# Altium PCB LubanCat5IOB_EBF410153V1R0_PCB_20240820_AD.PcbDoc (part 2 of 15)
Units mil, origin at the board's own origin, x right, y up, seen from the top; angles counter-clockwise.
Board outline 6811.02 x 4055.12 mil, 6 copper layers (TOP, GND02, ART03, ART04, PWR05, BOTTOM), stack 59.279 mil thick; 981 components, 783 nets, 3627 pads, 2669 vias.
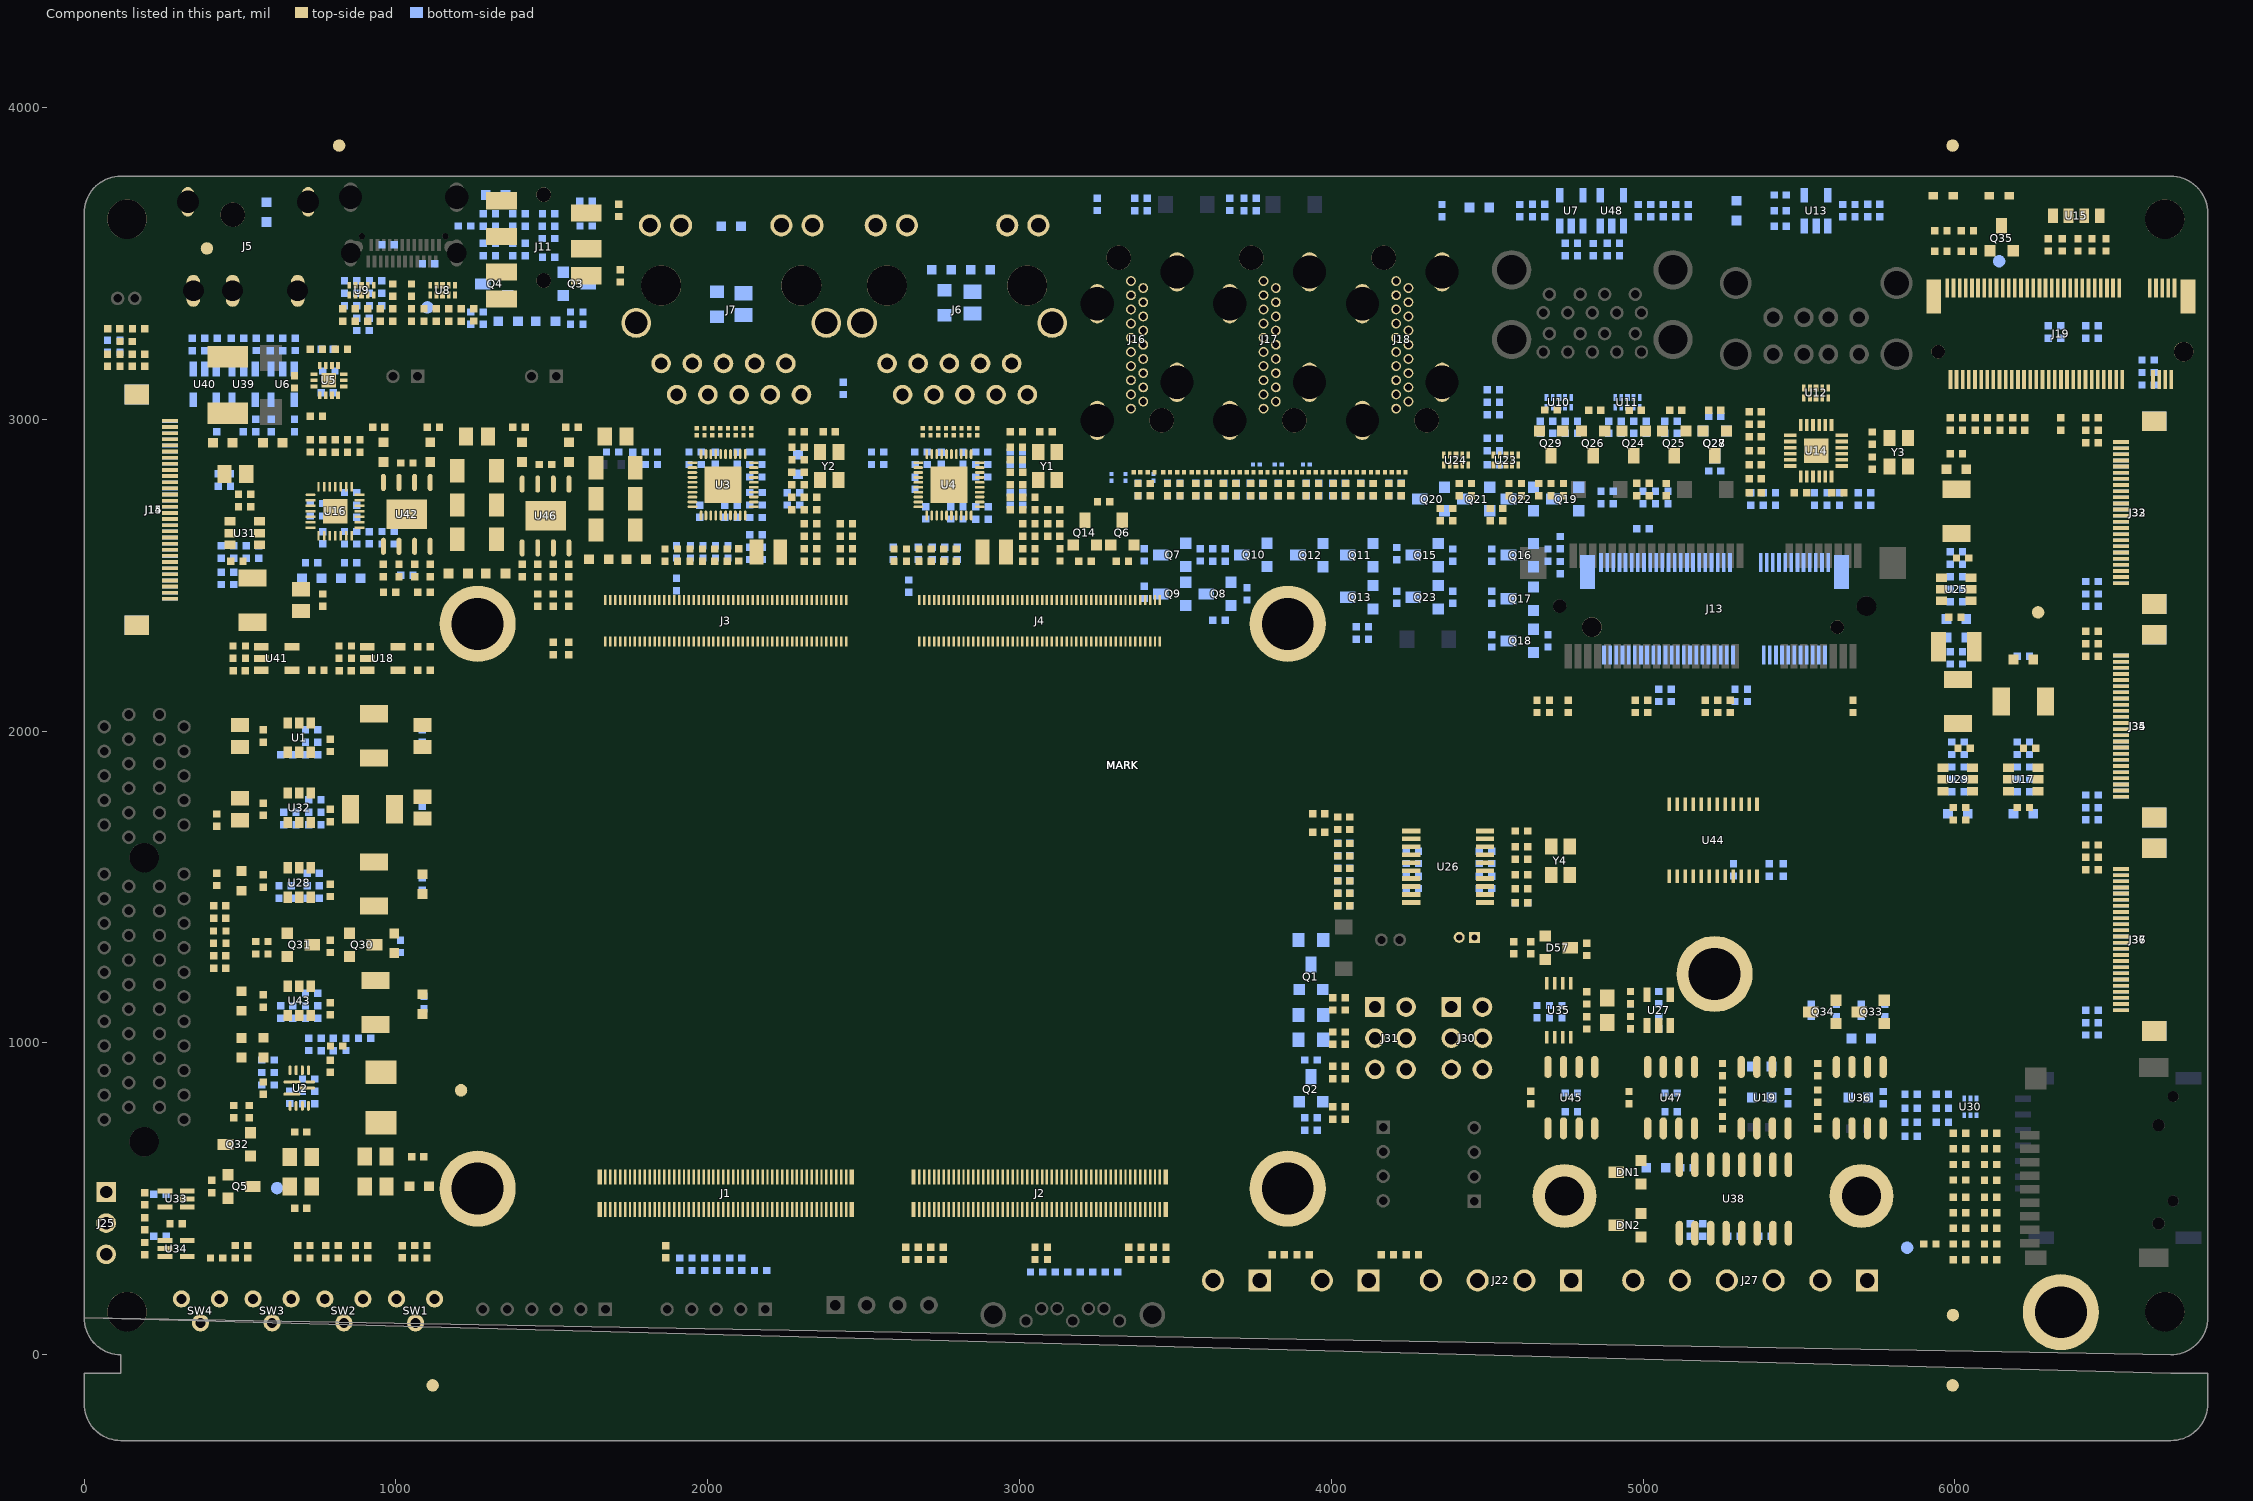
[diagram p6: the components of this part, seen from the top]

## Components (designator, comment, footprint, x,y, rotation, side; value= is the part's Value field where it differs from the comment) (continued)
Q9 "2SK3018_SOT23_IC_2SK3018" SOT23#1 3490,2440 r270 bottom
Q10 "2SK3018_SOT23_IC_2SK3018" SOT23#1 3750,2565 r270 bottom
Q11 "2SK3018_SOT23_IC_2SK3018" SOT23#1 4090,2564.37 r270 bottom
Q12 "2SK3018_SOT23_IC_2SK3018" SOT23#1 3930,2564.37 r270 bottom
Q13 "2SK3018_SOT23_IC_2SK3018" SOT23#1 4090,2429.37 r270 bottom
Q14 "2SK3018_SOT23_IC_2SK3018" SOT23#1 3210,2640 r0 top
Q15 "2SK3018_SOT23_IC_2SK3018" SOT23#1 4300,2564.37 r270 bottom
Q16 "2SK3018_SOT23_IC_2SK3018" SOT23#1 4605,2564.37 r270 bottom
Q17 "2SK3018_SOT23_IC_2SK3018" SOT23#1 4605,2424.37 r270 bottom
Q18 "2SK3018_SOT23_IC_2SK3018" SOT23#1 4605,2289.37 r270 bottom
Q19 "2SK3018_SOT23_IC_2SK3018" SOT23#1 4750,2744.37 r270 bottom
Q20 "2SK3018_SOT23_IC_2SK3018" SOT23#1 4320,2744.37 r270 bottom
Q21 "2SK3018_SOT23_IC_2SK3018" SOT23#1 4465,2744.37 r270 bottom
Q22 "2SK3018_SOT23_IC_2SK3018" SOT23#1 4605,2744.37 r270 bottom
Q23 "2SK3018_SOT23_IC_2SK3018" SOT23#1 4300,2429.37 r270 bottom
Q24 "2SK3018_SOT23_IC_2SK3018" SOT23#1 4970,2919.37 r180 top
Q25 "2SK3018_SOT23_IC_2SK3018" SOT23#1 5100,2919.37 r180 top
Q26 "2SK3018_SOT23_IC_2SK3018" SOT23#1 4840,2919.37 r180 top
Q27 "MOSFET_P_SOT23_IC_SSM3J328R-LF" SOT23#1 5230,2919.37 r180 top
Q28 "NPN_SOT23_IC_SS8050" SOT23#1 5230,2919.37 r0 bottom
Q29 "NPN_SOT23_IC_SS8050" SOT23#1 4705,2919.37 r180 top
Q30 "MOSFET_P_SOT23_IC_SSM3J328R-LF" SOT23#1 895,1314.37 r270 top
Q31 "NPN_SOT23_IC_SS8050" SOT23#1 695,1314.37 r270 top
Q32 "NPN_SOT23_IC_SS8050" SOT23#1 490,674.37 r90 top
Q33 "2SK3018_SOT23_IC_2SK3018" SOT23#1 5730,1099.37 r90 top
Q34 "2SK3018_SOT23_IC_2SK3018" SOT23#1 5575,1099.37 r90 top
Q35 "NPN_SOT23_IC_SS8050" SOT23#1 6150,3584.37 r0 top
R1 "RES_R0402_DISCRETE_100R" R0402#1 1020,330 r90 top
R2 "RES_R0402_DISCRETE_100R" R0402#1 890,350 r0 top
R3 "RES_R0402_DISCRETE_10K" R0402#1 4740,1100 r270 bottom
R4 "RES_R0402_DISCRETE_115K" R0402#1 730,1924.37 r0 bottom
R5 "RES_R0402_DISCRETE_100R" R0402#1 795,350 r0 top
R6 "RES_R0402_DISCRETE_1K" R0402#2 650,1924.37 r0 bottom
R7 "RES_R0402_DISCRETE_20K" R0402#1 730,2004.37 r0 bottom
R8 "RES_R0402_DISCRETE_3.3R" R0402#1 790,925.04 r90 top
R9 "RES_R0402_DISCRETE_510K" R0402#1 590,945.04 r0 bottom
R10 "RES_R0402_DISCRETE_NC" R0402#2 900,1015 r0 bottom
R11 "RES_R0402_DISCRETE_4.7K" R0402#1 5955,3604.37 r0 top
R12 "RES_R0402_DISCRETE_43K" R0402#2 780,975.04 r0 bottom
R13 "RES_R0402_DISCRETE_NC" R0402#1 780,1015.04 r0 bottom
R14 "RES_R0402_DISCRETE_100K" R0402#1 720,845.04 r0 bottom
R15 "RES_R0402_DISCRETE_100K" R0402#1 660,825.04 r270 bottom
R16 "RES_R0402_DISCRETE_100K" R0402#2 590,905.04 r0 bottom
R17 "RES_R0402_DISCRETE_7.5K" R0402#1 720,995.04 r90 bottom
R18 "RES_R0402_DISCRETE_NC" R0402#2 720,805.04 r0 bottom
R19 "RES_R0402_DISCRETE_100R" R0402#1 505,350 r0 top
R20 "RES_R0402_DISCRETE_4.7K" R0402#1 2720,2570 r270 bottom
R21 "RES_R0402_DISCRETE_4.7K" R0402#1 2675,2570 r270 bottom
R22 "RES_R0402_DISCRETE_4.7K" R0402#1 2595,2570 r270 bottom
R23 "RES_R0402_DISCRETE_22R" R0402#1 2717.62,2564.37 r90 top
R24 "RES_R0402_DISCRETE_22R" R0402#1 2677.62,2564.37 r90 top
R25 "RES_R0402_DISCRETE_2.49K" R0402#2 2879,2855 r0 bottom
R26 "RES_R0402_DISCRETE_22R" R0402#1 2637.62,2564.37 r90 top
R27 "RES_R0402_DISCRETE_22R" R0402#1 2597.62,2564.37 r90 top
R28 "RES_R0402_DISCRETE_22R" R0402#1 2797.62,2564.37 r90 top
R29 "RES_R0402_DISCRETE_22R" R0402#1 2757.62,2564.37 r90 top
R30 "RES_R0402_DISCRETE_4.7K" R0402#1 2645,2465 r270 bottom
R31 "RES_R0402_DISCRETE_4.7K" R0402#1 2800,2570 r90 bottom
R32 "RES_R0402_DISCRETE_4.7K" R0402#1 2760,2570 r90 bottom
R33 "RES_R0402_DISCRETE_4.7K" R0402#1 2545,2895 r0 bottom
R34 "RES_R0402_DISCRETE_4.7K" R0402#1 2545,2855 r0 bottom
R35 "RES_R0402_DISCRETE_4.7K" R0402#1 2880,2680 r0 bottom
R36 "RES_R0402_DISCRETE_115K" R0402#1 520,2574.37 r270 bottom
R37 "RES_R0402_DISCRETE_22R" R0402#1 2970,2745 r90 bottom
R38 "RES_R0402_DISCRETE_NC" R0402#1 3010,2745 r90 bottom
R39 "RES_R0603_DISCRETE_510R" R0603#1 2750,3479.37 r0 bottom
R40 "RES_R0603_DISCRETE_510R" R0603#2 2875,3479.37 r0 bottom
R41 "RES_R0402_DISCRETE_10K" R0402#1 2665,2795 r90 bottom
R42 "RES_R0805_DISCRETE_1M" R0805#1 2760,3374.37 r90 bottom
R43 "RES_R0402_DISCRETE_4.7K" R0402#1 2990,2855 r0 bottom
R44 "RES_R0402_DISCRETE_4.7K" R0402#1 2970,2730 r90 top
R45 "RES_R0402_DISCRETE_4.7K" R0402#2 2880,2720 r0 bottom
R46 "RES_R0402_DISCRETE_0R" R0402#1 3010,2645 r270 top
R47 "RES_R0402_DISCRETE_0R" R0402#1 3050,2645 r90 top
R48 "RES_R0402_DISCRETE_4.7K" R0402#1 1985,2575 r270 bottom
R49 "RES_R0402_DISCRETE_4.7K" R0402#1 1945,2575 r270 bottom
R50 "RES_R0402_DISCRETE_4.7K" R0402#1 1900,2575 r270 bottom
R51 "RES_R0402_DISCRETE_22R" R0402#1 1983.21,2564.37 r90 top
R52 "RES_R0402_DISCRETE_22R" R0402#1 1943.21,2564.37 r90 top
R53 "RES_R0402_DISCRETE_2.49K" R0402#2 2154.59,2855 r0 bottom
R54 "RES_R0402_DISCRETE_22R" R0402#1 1903.21,2564.37 r90 top
R55 "RES_R0402_DISCRETE_22R" R0402#1 1863.21,2564.37 r90 top
R56 "RES_R0402_DISCRETE_22R" R0402#1 2063.21,2564.37 r90 top
R57 "RES_R0402_DISCRETE_22R" R0402#1 2023.21,2564.37 r90 top
R58 "RES_R0402_DISCRETE_4.7K" R0402#1 1900,2470 r270 bottom
R59 "RES_R0402_DISCRETE_4.7K" R0402#1 2065,2575 r90 bottom
R60 "RES_R0402_DISCRETE_4.7K" R0402#1 2025,2575 r90 bottom
R61 "RES_R0402_DISCRETE_4.7K" R0402#1 1819.59,2895 r0 bottom
R62 "RES_R0402_DISCRETE_4.7K" R0402#1 1819.59,2855 r0 bottom
R63 "RES_R0402_DISCRETE_4.7K" R0402#1 2155,2685 r0 bottom
R64 "RES_R0603_DISCRETE_510R" R0603#1 2290,2855 r270 bottom
R65 "RES_R0402_DISCRETE_1K" R0402#1 440,2574.37 r270 bottom
R66 "RES_R0603_DISCRETE_510R" R0603#1 2075,3619.37 r0 bottom
R67 "RES_R0402_DISCRETE_100R" R0402#1 2255,2745 r90 bottom
R68 "RES_R0402_DISCRETE_120R" R0402#1 2295,2745 r90 bottom
R69 "RES_R0402_DISCRETE_10K" R0402#1 1695,2895 r0 bottom
R70 "RES_R0402_DISCRETE_NC" R0402#1 1760,2875 r90 bottom
R71 "RES_R0805_DISCRETE_1M" R0805#1 2030,3369.37 r90 bottom
R72 "RES_R0402_DISCRETE_4.7K" R0402#1 2270,2730 r90 top
R73 "RES_R0402_DISCRETE_4.7K" R0402#2 2155,2765 r0 bottom
R74 "RES_R0402_DISCRETE_4.7K" R0402#2 2155,2725 r0 bottom
R75 "RES_R0402_DISCRETE_0R" R0402#1 2350,2645 r270 top
R76 "RES_R0402_DISCRETE_0R" R0402#1 2310,2645 r90 top
R77 "RES_R0402_DISCRETE_4.7K" R0402#1 2445,2545 r180 top
R78 "RES_R0402_DISCRETE_NC" R0402#1 2445,2585 r180 top
R79 "RES_R0402_DISCRETE_2.2R" R0402#1 4790,2974.37 r270 bottom
R80 "RES_R0402_DISCRETE_2.2R" R0402#1 4750,2974.37 r270 bottom
R81 "RES_R0402_DISCRETE_2.2R" R0402#1 1050,3334.37 r270 top
R82 "RES_R0402_DISCRETE_2.2R" R0402#1 990,3334.37 r270 top
R83 "RES_R0402_DISCRETE_0R" R0402#1 4710,2974.37 r270 bottom
R84 "RES_R0402_DISCRETE_0R" R0402#1 4670,2974.37 r270 bottom
R85 "RES_R0402_DISCRETE_0R" R0402#1 1170,3334.37 r270 top
R86 "RES_R0402_DISCRETE_0R" R0402#1 1210,3334.37 r270 top
R87 "RES_R0402_DISCRETE_10K" R0402#1 745,3010 r0 top
R88 "RES_R0402_DISCRETE_2.2R" R0402#1 4930,2974.37 r270 bottom
R89 "RES_R0402_DISCRETE_0R" R0402#1 910,3334.37 r270 top
R90 "RES_R0402_DISCRETE_2.2R" R0402#1 4890,2974.37 r270 bottom
R91 "RES_R0402_DISCRETE_0R" R0402#1 950,3334.37 r270 top
R92 "RES_R0402_DISCRETE_100K" R0402#1 935,3364.37 r0 bottom
R93 "RES_R0402_DISCRETE_1K" R0402#1 600,2980 r90 bottom
R94 "RES_R0402_DISCRETE_100K" R0402#2 855,3364.37 r0 bottom
R95 "RES_R0402_DISCRETE_3.4K" R0402#1 677,3240.37 r90 bottom
R96 "RES_R0402_DISCRETE_1K" R0402#1 4605,3669.37 r90 bottom
R97 "RES_R0402_DISCRETE_NC" R0402#1 935,3404.37 r0 bottom
R98 "RES_R0402_DISCRETE_NC" R0402#2 855,3404.37 r0 bottom
R99 "RES_R0402_DISCRETE_3.4K" R0402#2 4665,3649.37 r0 bottom
R100 "RES_R0402_DISCRETE_0R" R0402#1 5385,2744.37 r90 bottom
R101 "RES_R0402_DISCRETE_10K" R0402#1 5360,2854.37 r180 top
R102 "RES_R0402_DISCRETE_1K" R0402#1 5440,3719.37 r0 bottom
R103 "RES_R0402_DISCRETE_3.4K" R0402#2 5440,3619.37 r0 bottom
R104 "RES_R0402_DISCRETE_100K" R0402#1 5360,2764.37 r180 top
R105 "RES_R0402_DISCRETE_100K" R0402#1 5360,2899.37 r180 top
R106 "RES_R0402_DISCRETE_2.2R" R0402#1 5360,2944.37 r180 top
R107 "RES_R0402_DISCRETE_2.2R" R0402#1 5360,2984.37 r180 top
R108 "RES_R0402_DISCRETE_2.7K" R0402#1 5360,3024.37 r180 top
R109 "RES_R0402_DISCRETE_10K" R0402#1 6345,3559.37 r90 top
R110 "RES_R0402_DISCRETE_22R" R0402#1 6300,3559.37 r90 top
R111 "RES_R0402_DISCRETE_22R" R0402#1 6485,3559.37 r270 top
R112 "RES_R0402_DISCRETE_4.7R" R0402#1 915,2620 r90 bottom
R113 "RES_R0402_DISCRETE_100R" R0402#1 1490,3519.37 r0 bottom
R114 "RES_R0402_DISCRETE_0R" R0402#1 1470,3599.37 r270 bottom
R115 "RES_R0402_DISCRETE_2.2K" R0402#2 1300,3619.37 r0 bottom
R116 "RES_R0402_DISCRETE_100K" R0402#1 1300,3659.37 r0 bottom
R117 "RES_R0402_DISCRETE_0R" R0402#1 1510,3599.37 r270 bottom
R118 "RES_R0402_DISCRETE_100K" R0402#1 1395,3659.37 r0 bottom
R119 "RES_R0402_DISCRETE_100K" R0402#1 1630,3679.37 r270 bottom
R120 "RES_R0402_DISCRETE_0R" R0402#1 1590,3679.37 r90 bottom
R121 "RES_R0402_DISCRETE_10K" R0402#1 725,2915 r270 top
R122 "RES_R0402_DISCRETE_0R" R0402#1 1560,3324.37 r270 bottom
R123 "RES_R0402_DISCRETE_470R" R0402#1 1600,3324.37 r270 bottom
R124 "RES_R0402_DISCRETE_0R" R0402#1 1280,3324.37 r270 bottom
R125 "RES_R0402_DISCRETE_100R" R0402#1 115,3234.37 r270 bottom
R126 "RES_R0402_DISCRETE_1.1K" R0402#1 75,3189.37 r90 top
R127 "RES_R0805_DISCRETE_0R" R0805#2 3935,1090 r0 bottom
R128 "RES_R0402_DISCRETE_4.7K" R0402#1 6040,3604.37 r0 top
R129 "RES_R0805_DISCRETE_0R" R0805#1 3935,1330 r0 bottom
R130 "RES_R0402_DISCRETE_0R" R0402#1 115,3189.37 r270 top
R131 "RES_R0805_DISCRETE_NC" R0805#2 3935,1010 r0 bottom
R132 "RES_R0402_DISCRETE_10K" R0402#1 3935,945 r0 bottom
R133 "RES_R0402_DISCRETE_1K" R0402#1 3935,720 r0 bottom
R134 "RES_R0402_DISCRETE_0R" R0402#1 155,3189.37 r270 top
R135 "RES_R0402_DISCRETE_10K" R0402#2 3935,760 r0 bottom
R136 "RES_R0402_DISCRETE_1.1K" R0402#1 195,3189.37 r270 top
R137 "RES_R0402_DISCRETE_0R" R0402#1 455,1339.37 r90 top
R138 "RES_R0402_DISCRETE_100K" R0402#2 6220,1925 r0 bottom
R139 "RES_R0402_DISCRETE_10K" R0402#2 6220,1805 r0 bottom
R140 "RES_R0402_DISCRETE_1K" R0402#2 6220,1845 r0 bottom
R141 "RES_R0402_DISCRETE_30K" R0402#2 6220,1885 r0 bottom
R142 "RES_R0402_DISCRETE_2.2R" R0402#1 5590,2744.37 r270 bottom
R143 "RES_R0402_DISCRETE_2.2R" R0402#1 5550,2744.37 r270 bottom
R144 "RES_R0402_DISCRETE_1K" R0402#1 5090,2114.37 r270 bottom
R145 "RES_R0402_DISCRETE_22R" R0402#1 5080,2749.37 r270 bottom
R146 "RES_R0402_DISCRETE_1K" R0402#1 5050,2114.37 r270 bottom
R147 "RES_R0402_DISCRETE_4.7K" R0402#1 5040,2749.37 r270 bottom
R148 "RES_R0402_DISCRETE_22R" R0402#1 5000,2749.37 r270 bottom
R149 "RES_R0402_DISCRETE_20K" R0402#1 5105,3669.37 r270 bottom
R150 "RES_R0402_DISCRETE_10K" R0402#1 5065,3669.37 r90 bottom
R151 "RES_R0402_DISCRETE_4.7K" R0402#1 3330,2545 r0 top
R152 "RES_R0402_DISCRETE_4.7K" R0402#1 3270,2735 r0 top
R153 "RES_R0402_DISCRETE_1K" R0402#2 3640,2585 r0 bottom
R154 "RES_R0402_DISCRETE_4.7K" R0402#2 3640,2545 r0 bottom
R155 "RES_R0402_DISCRETE_4.7K" R0402#1 3400,2565 r90 bottom
R156 "RES_R0402_DISCRETE_0R" R0402#1 3250,3689.37 r90 bottom
R157 "RES_R0402_DISCRETE_47K" R0402#2 3640,2355 r0 bottom
R158 "RES_R0402_DISCRETE_47K" R0402#1 3730,2440 r90 bottom
R159 "RES_R0402_DISCRETE_1.2K" R0402#1 3380,2775 r90 bottom
R160 "RES_R0402_DISCRETE_47K" R0402#1 3400,2445 r270 bottom
R161 "RES_R0402_DISCRETE_499R" R0402#1 3475,2775 r270 bottom
R162 "RES_R0402_DISCRETE_499R" R0402#1 3515,2775 r270 bottom
R163 "RES_R0402_DISCRETE_499R" R0402#1 3740,2775 r270 bottom
R164 "RES_R0402_DISCRETE_499R" R0402#1 3780,2775 r270 bottom
R165 "RES_R0402_DISCRETE_499R" R0402#1 3655,2775 r270 bottom
R166 "RES_R0402_DISCRETE_499R" R0402#1 3695,2775 r270 bottom
R167 "RES_R0402_DISCRETE_499R" R0402#1 3565,2775 r270 bottom
R168 "RES_R0402_DISCRETE_499R" R0402#1 3605,2775 r270 bottom
R169 "RES_R0402_DISCRETE_1K" R0402#1 4100,2294.37 r0 bottom
R170 "RES_R0402_DISCRETE_27K" R0402#1 3210,2545 r0 top
R171 "RES_R0402_DISCRETE_10K" R0402#2 4100,2334.37 r0 bottom
R172 "RES_R0402_DISCRETE_4.7K" R0402#1 4390,2564.37 r270 bottom
R173 "RES_R0402_DISCRETE_10K" R0402#1 4210,2569.37 r90 bottom
R174 "RES_R0402_DISCRETE_1K" R0402#1 4735,2604.37 r270 bottom
R175 "RES_R0402_DISCRETE_4.7K" R0402#1 4735,2524.37 r90 bottom
R176 "RES_R0402_DISCRETE_10K" R0402#1 4515,2564.37 r90 bottom
R177 "RES_R0402_DISCRETE_0R" R0402#1 3675,3689.37 r90 bottom
R178 "RES_R0402_DISCRETE_47K" R0402#1 4515,2429.37 r270 bottom
R179 "RES_R0402_DISCRETE_47K" R0402#1 4515,2289.37 r90 bottom
R180 "RES_R0402_DISCRETE_1.2K" R0402#1 3830,2775 r90 bottom
R181 "RES_R0402_DISCRETE_47K" R0402#1 4695,2289.37 r270 bottom
R182 "RES_R0402_DISCRETE_499R" R0402#1 3920,2775 r270 bottom
R183 "RES_R0402_DISCRETE_499R" R0402#1 3960,2775 r270 bottom
R184 "RES_R0402_DISCRETE_499R" R0402#1 4185,2775 r270 bottom
R185 "RES_R0402_DISCRETE_499R" R0402#1 4225,2775 r270 bottom
R186 "RES_R0402_DISCRETE_499R" R0402#1 4095,2775 r270 bottom
R187 "RES_R0402_DISCRETE_499R" R0402#1 4135,2774.37 r270 bottom
R188 "RES_R0402_DISCRETE_499R" R0402#1 4005,2775 r270 bottom
R189 "RES_R0402_DISCRETE_499R" R0402#1 4045,2775 r270 bottom
R190 "RES_R0402_DISCRETE_1K" R0402#1 4905,2749.37 r90 bottom
R191 "RES_R0402_DISCRETE_27K" R0402#1 4390,2429.37 r270 bottom
R192 "RES_R0402_DISCRETE_10K" R0402#1 4865,2749.37 r270 bottom
R193 "RES_R0402_DISCRETE_100K" R0402#1 4745,2774.37 r90 top
R194 "RES_R0402_DISCRETE_22K" R0402#1 4705,2774.37 r270 top
R195 "RES_R0402_DISCRETE_0R" R0402#1 4355,3669.37 r90 bottom
R196 "RES_R0402_DISCRETE_10K" R0402#1 4975,3029.37 r180 top
R197 "RES_R0402_DISCRETE_47K" R0402#1 5000,2754.37 r0 top
R198 "RES_R0402_DISCRETE_56K" R0402#1 5105,3029.37 r180 top
R199 "RES_R0402_DISCRETE_10K" R0402#1 4845,3029.37 r180 top
R200 "RES_R0402_DISCRETE_47K" R0402#1 5000,2794.37 r0 top
R201 "RES_R0402_DISCRETE_2.2R" R0402#1 4610,2774.37 r90 top
R202 "RES_R0402_DISCRETE_2.2R" R0402#1 4570,2774.37 r90 top
R203 "RES_R0402_DISCRETE_2.2R" R0402#1 4550,2694.37 r90 top
R204 "RES_R0402_DISCRETE_2.2R" R0402#1 4510,2694.37 r90 top
R205 "RES_R0402_DISCRETE_2.2R" R0402#1 4450,2774.37 r90 top
R206 "RES_R0402_DISCRETE_2.2R" R0402#1 4410,2774.37 r90 top
R207 "RES_R0402_DISCRETE_2.2R" R0402#1 4390,2694.37 r90 top
R208 "RES_R0402_DISCRETE_2.2R" R0402#1 4350,2694.37 r90 top
R209 "RES_R0402_DISCRETE_56K" R0402#1 5075,2774.37 r90 top
R210 "RES_R0402_DISCRETE_100K" R0402#1 4665,2774.37 r90 top
R211 "RES_R0402_DISCRETE_20K" R0402#1 5110,2974.37 r90 bottom
R212 "RES_R0402_DISCRETE_10K" R0402#1 5070,2974.37 r270 bottom
R213 "RES_R0402_DISCRETE_100K" R0402#1 5230,3029.37 r0 top
R214 "RES_R0402_DISCRETE_1K" R0402#2 5230,2834.37 r0 bottom
R215 "RES_R0402_DISCRETE_10K" R0402#2 5230,3009.37 r0 bottom
R216 "RES_R0402_DISCRETE_33R" R0402#1 4040,1439.37 r180 top
R217 "RES_R0402_DISCRETE_33R" R0402#1 4040,1479.37 r180 top
R218 "RES_R0402_DISCRETE_100K" R0402#2 6005,2535 r0 bottom
R219 "RES_R0402_DISCRETE_49.9R" R0402#1 4040,1480 r0 bottom
R220 "RES_R0402_DISCRETE_49.9R" R0402#1 4040,1440 r0 bottom
R221 "RES_R0402_DISCRETE_1K" R0402#2 6005,2455 r0 bottom
R222 "RES_R0402_DISCRETE_10K" R0402#2 6005,2415 r0 bottom
R223 "RES_R0402_DISCRETE_10K" R0402#1 4475,1595 r90 bottom
R224 "RES_R0402_DISCRETE_4.7K" R0402#1 4515,1595 r90 bottom
R225 "RES_R0402_DISCRETE_10K" R0402#1 4475,1515 r270 bottom
R226 "RES_R0402_DISCRETE_10K" R0402#1 4515,1515 r270 bottom
R227 "RES_R0402_DISCRETE_30K" R0402#2 6005,2495 r0 bottom
R228 "RES_R0402_DISCRETE_33R" R0402#1 4040,1519.37 r180 top
R229 "RES_R0402_DISCRETE_33R" R0402#1 4040,1559.37 r180 top
R230 "RES_R0402_DISCRETE_22R" R0402#1 4610,1589.37 r180 top
R231 "RES_R0402_DISCRETE_49.9R" R0402#1 4040,1560 r0 bottom
R232 "RES_R0402_DISCRETE_49.9R" R0402#1 4040,1520 r0 bottom
R233 "RES_R0402_DISCRETE_10K" R0402#1 4610,1494.37 r0 top
R234 "RES_R0402_DISCRETE_470R" R0402#1 4610,1679.37 r0 top
R235 "RES_R0402_DISCRETE_2.2R" R0402#1 4280,1595 r270 bottom
R236 "RES_R0402_DISCRETE_10K" R0402#1 6065,2985 r270 top
R237 "RES_R0402_DISCRETE_10K" R0402#1 6340,2985 r270 top
R238 "RES_R0402_DISCRETE_33R" R0402#1 4040,1599.37 r180 top
R239 "RES_R0402_DISCRETE_33R" R0402#1 4040,1639.37 r180 top
R240 "RES_R0402_DISCRETE_49.9R" R0402#1 4040,1640 r0 bottom
R241 "RES_R0402_DISCRETE_49.9R" R0402#1 4040,1600 r0 bottom
R242 "RES_R0402_DISCRETE_33R" R0402#1 4040,1724.37 r180 top
R243 "RES_R0402_DISCRETE_33R" R0402#1 4040,1684.37 r180 top
R244 "RES_R0402_DISCRETE_49.9R" R0402#1 3960,1675 r180 top
R245 "RES_R0402_DISCRETE_49.9R" R0402#1 3960,1735 r180 top
R246 "RES_R0402_DISCRETE_1K" R0402#1 5050,1065 r270 bottom
R247 "RES_R0402_DISCRETE_0R" R0402#1 425,1714.37 r270 top
R248 "RES_R0402_DISCRETE_0R" R0402#1 425,1524.37 r270 top
R249 "RES_R0402_DISCRETE_100K" R0402#1 735,1464.37 r0 bottom
R250 "RES_R0402_DISCRETE_30K" R0402#1 735,1544.37 r0 bottom
R251 "RES_R0402_DISCRETE_1K" R0402#2 645,1464.37 r0 bottom
R252 "RES_R0402_DISCRETE_10K" R0402#2 645,1504.37 r0 bottom
R253 "RES_R0402_DISCRETE_15K" R0402#1 5860,700 r0 bottom
R254 "RES_R0402_DISCRETE_100K" R0402#1 6010,1925 r0 bottom
R255 "RES_R0402_DISCRETE_10K" R0402#1 790,1309.37 r90 top
R256 "RES_R0402_DISCRETE_1K" R0402#1 570,1325 r0 top
R257 "RES_R0402_DISCRETE_10K" R0402#1 570,1285 r180 top
R258 "RES_R0402_DISCRETE_0R" R0402#1 5860,835 r0 bottom
R259 "RES_R0402_DISCRETE_0R" R0402#1 5860,790 r0 bottom
R260 "RES_R0402_DISCRETE_0R" R0402#1 5860,745 r0 bottom
R261 "RES_R0402_DISCRETE_30K" R0402#2 6010,1885 r0 bottom
R262 "RES_R0402_DISCRETE_1K" R0402#1 6010,1845 r0 bottom
R263 "RES_R0402_DISCRETE_10K" R0402#2 6010,1805 r0 bottom
R264 "RES_R0402_DISCRETE_4.7K" R0402#1 5690,2744.37 r270 bottom
R265 "RES_R0402_DISCRETE_22R" R0402#1 5730,2744.37 r270 bottom
R266 "RES_R0402_DISCRETE_22R" R0402#1 5630,2744.37 r270 bottom
R267 "RES_R0402_DISCRETE_1K" R0402#1 5280,2079.37 r270 top
R268 "RES_R0402_DISCRETE_1K" R0402#1 5240,2079.37 r270 top
R269 "RES_R0402_DISCRETE_2.2R" R0402#1 5015,2079.37 r270 top
R270 "RES_R0402_DISCRETE_2.2R" R0402#1 4975,2079.37 r270 top
R271 "RES_R0402_DISCRETE_20K" R0402#1 560,2574.37 r270 bottom
R272 "RES_R0402_DISCRETE_100K" R0402#1 740,1699.37 r0 bottom
R273 "RES_R0402_DISCRETE_1K" R0402#2 660,1699.37 r0 bottom
R274 "RES_R0402_DISCRETE_30K" R0402#1 740,1779.37 r0 bottom
R275 "RES_R0402_DISCRETE_22R" R0402#1 6015,710 r0 top
R276 "RES_R0402_DISCRETE_10K" R0402#1 4700,1100 r90 bottom
R277 "RES_R0402_DISCRETE_22R" R0402#1 4660,1100 r270 bottom
R278 "RES_R0402_DISCRETE_22R" R0402#1 6015,660 r0 top
R279 "RES_R0402_DISCRETE_22R" R0402#1 6015,610 r0 top
R280 "RES_R0402_DISCRETE_0R" R0402#1 6015,505 r0 top
R281 "RES_R0402_DISCRETE_22R" R0402#1 6015,455 r0 top
R282 "RES_R0402_DISCRETE_22R" R0402#1 6015,405 r0 top
R283 "RES_R0402_DISCRETE_100R" R0402#1 6015,355 r0 top
R284 "RES_R0402_DISCRETE_NC" R0402#1 5920,355 r0 top
R285 "RES_R0402_DISCRETE_0R" R0402#1 6115,305 r180 top
R286 "RES_R0402_DISCRETE_0R" R0402#1 6420,2985 r270 top
R287 "RES_R0402_DISCRETE_4.7K" R0402#1 5560,744.37 r270 top
R288 "RES_R0402_DISCRETE_120R" R0402#1 5560,829.37 r270 top
R289 "RES_R0603_DISCRETE_10K" R0603#1 5700,1014.37 r0 bottom
R290 "RES_R0402_DISCRETE_100R" R0402#1 195,500 r90 top
R291 "RES_R0402_DISCRETE_100R" R0402#1 195,340 r270 top
R292 "RES_R0402_DISCRETE_4.7K" R0402#1 5560,914.37 r90 top
R293 "RES_R0402_DISCRETE_4.7K" R0402#1 5255,744.37 r270 top
R294 "RES_R0402_DISCRETE_120R" R0402#1 5255,829.37 r270 top
R295 "RES_R0603_DISCRETE_10K" R0603#1 5380,924.37 r0 bottom
R296 "RES_R0402_DISCRETE_4.7K" R0402#1 5255,914.37 r90 top
R297 "RES_R0402_DISCRETE_100R" R0402#1 4005,905 r270 top
R298 "RES_R0402_DISCRETE_100R" R0402#1 4005,775 r90 top
R299 "RES_R0402_DISCRETE_100R" R0402#1 4005,1125 r270 top
R300 "RES_R0402_DISCRETE_100R" R0402#1 4005,1015 r270 top
R301 "RES_R0402_DISCRETE_NC" R0402#2 450,2785 r0 bottom
R302 "RES_R0402_DISCRETE_NC" R0402#1 440,2490 r90 bottom
R303 "RES_R0402_DISCRETE_NC" R0402#2 450,2825 r0 bottom
R304 "RES_R0402_DISCRETE_NC" R0402#1 480,2490 r90 bottom
R305 "RES_R0402_DISCRETE_1K" R0402#1 1090,2270 r180 top
R306 "RES_R0402_DISCRETE_1K" R0402#1 510,2980 r90 bottom
R307 "RES_R0402_DISCRETE_3.4K" R0402#1 837.63,2193 r180 top
R308 "RES_R0402_DISCRETE_3.4K" R0402#1 552,3240.37 r90 bottom
R309 "RES_R0402_DISCRETE_3.4K" R0402#1 427,3240.37 r90 bottom
R310 "RES_R0402_DISCRETE_3.4K" R0402#1 497.63,2193 r180 top
R311 "RES_R0402_DISCRETE_0R" R0402#1 6420,2420 r90 bottom
R312 "RES_R0402_DISCRETE_0R" R0402#1 6420,2300 r270 top
R313 "RES_R0402_DISCRETE_0R" R0402#1 6420,1735 r90 bottom
R314 "RES_R0402_DISCRETE_0R" R0402#1 6420,1615 r270 top
R315 "RES_R0402_DISCRETE_0R" R0402#1 6420,1045 r90 bottom
R316 "RES_R0402_DISCRETE_115K" R0402#1 730,1079.37 r0 bottom
R317 "RES_R0402_DISCRETE_10K" R0402#2 650,1119.37 r0 bottom
R318 "RES_R0402_DISCRETE_1K" R0402#2 650,1079.37 r0 bottom
R319 "RES_R0402_DISCRETE_10K" R0402#1 410,539.37 r90 top
R320 "RES_R0402_DISCRETE_1K" R0402#1 480,779.37 r270 top
R321 "RES_R0402_DISCRETE_10K" R0402#1 530,779.37 r90 top
R322 "RES_R0402_DISCRETE_20K" R0402#1 730,1159.37 r0 bottom
R323 "RES_R0402_DISCRETE_3.4K" R0402#1 4840,3544.37 r270 bottom
R324 "RES_R0402_DISCRETE_1K" R0402#1 5025,3669.37 r90 bottom
R325 "RES_R0402_DISCRETE_470R" R0402#1 1240,3324.37 r270 bottom
R326 "RES_R0402_DISCRETE_300K" R0402#2 1300,3524.37 r0 bottom
R327 "RES_R0402_DISCRETE_0R" R0402#1 1300,3564.37 r0 bottom
R328 "RES_R0402_DISCRETE_10K" R0402#1 415,1339.37 r90 top
R329 "RES_R0402_DISCRETE_2.2K" R0402#1 5775,1104.37 r90 bottom
R330 "RES_R0402_DISCRETE_10K" R0402#1 5700,1104.37 r90 bottom
R331 "RES_R0402_DISCRETE_10K" R0402#1 5540,1104.37 r90 bottom
R332 "RES_R0402_DISCRETE_2.2K" R0402#1 5620,1104.37 r90 bottom
R333 "RES_R0402_DISCRETE_120R" R0402#1 4640,825 r270 top
R334 "RES_R0402_DISCRETE_1K" R0402#1 5955,3539.37 r0 top
R335 "RES_R0402_DISCRETE_10K" R0402#1 6040,3539.37 r180 top
R336 "RES_R0402_DISCRETE_25.5K" R0402#1 1505,2265 r90 top
R337 "RES_R0402_DISCRETE_10K" R0402#1 1555,2265 r270 top
R338 "RES_R0402_DISCRETE_100R" R0402#1 2090,310 r0 bottom
R339 "RES_R0402_DISCRETE_100R" R0402#1 2010,310 r0 bottom
R340 "RES_R0402_DISCRETE_100R" R0402#1 1930,310 r0 bottom
R341 "RES_R0603_DISCRETE_0R" R0603#1 1320,2505 r180 top
R342 "RES_R0603_DISCRETE_NC" R0603#1 1200,2505 r0 top
R343 "RES_R0402_DISCRETE_20K" R0402#1 1110,2515 r90 top
R344 "RES_R0402_DISCRETE_20K" R0402#1 1060,2515 r90 top
R345 "RES_R0402_DISCRETE_1K" R0402#1 980,2445 r180 top
R346 "RES_R0402_DISCRETE_10K" R0402#1 960,2515 r270 top
R347 "RES_R0603_DISCRETE_0R" R0603#1 1771,2551 r180 top
R348 "RES_R0603_DISCRETE_NC" R0603#1 1651,2551 r0 top
R349 "RES_R0402_DISCRETE_20K" R0402#1 1555,2515 r90 top
R350 "RES_R0402_DISCRETE_20K" R0402#1 1505,2515 r90 top
R351 "RES_R0402_DISCRETE_1K" R0402#1 1455,2420 r90 top
R352 "RES_R0402_DISCRETE_10K" R0402#1 1405,2515 r270 top
R353 "RES_R0402_DISCRETE_10K" R0402#1 5290,1555 r270 bottom
R354 "RES_R0402_DISCRETE_27K" R0402#1 4210,2429.37 r90 bottom
R355 "RES_R0402_DISCRETE_120R" R0402#1 4955,824.37 r270 top
R356 "RES_R0402_DISCRETE_2.2K" R0402#1 3430,325 r90 top
R357 "RES_R0402_DISCRETE_2.2K" R0402#1 3470,325 r90 top
R358 "RES_R0402_DISCRETE_2.2K" R0402#1 3350,325 r90 top
R359 "RES_R0402_DISCRETE_2.2K" R0402#1 3390,325 r90 top
R360 "RES_R0402_DISCRETE_2.2K" R0402#1 3050,325 r90 top
R361 "RES_R0402_DISCRETE_2.2K" R0402#1 3090,325 r90 top
R362 "RES_R0402_DISCRETE_0R" R0402#1 1865,330 r90 top
R363 "RES_R0402_DISCRETE_0R" R0402#1 3130,2565 r270 top
R364 "RES_R0402_DISCRETE_0R" R0402#1 3085,2960 r0 top
R365 "RES_R0201_DISCRETE_0R" R0201#1 2864.41,2960 r90 top
R366 "RES_R0201_DISCRETE_0R" R0201#1 2839.41,2960 r90 top
R367 "RES_R0201_DISCRETE_0R" R0201#1 2814.41,2960 r90 top
R368 "RES_R0201_DISCRETE_0R" R0201#1 2789.41,2960 r90 top
R369 "RES_R0201_DISCRETE_0R" R0201#1 2764.41,2960 r90 top
R370 "RES_R0201_DISCRETE_0R" R0201#1 2739.41,2960 r90 top
R371 "RES_R0201_DISCRETE_0R" R0201#1 2714.41,2960 r90 top
R372 "RES_R0201_DISCRETE_0R" R0201#1 2689.41,2960 r90 top
R373 "RES_R0201_DISCRETE_0R" R0201#1 2140,2960 r90 top
R374 "RES_R0201_DISCRETE_0R" R0201#1 2115,2960 r90 top
R375 "RES_R0201_DISCRETE_0R" R0201#1 2090,2960 r90 top
R376 "RES_R0201_DISCRETE_0R" R0201#1 2065,2960 r90 top
R377 "RES_R0201_DISCRETE_0R" R0201#1 2040,2960 r90 top
R378 "RES_R0201_DISCRETE_0R" R0201#1 2015,2960 r90 top
R379 "RES_R0201_DISCRETE_0R" R0201#1 1990,2960 r90 top
R380 "RES_R0201_DISCRETE_0R" R0201#1 1965,2960 r90 top
R381 "RES_R0402_DISCRETE_0R" R0402#1 2445,2625 r0 top
R382 "RES_R0402_DISCRETE_0R" R0402#1 2175,2570 r270 bottom
R383 "RES_R0402_DISCRETE_0R" R0402#1 2390,2960 r0 top
R384 "RES_R0402_DISCRETE_22R" R0402#1 2990,2870 r180 top
R385 "RES_R0402_DISCRETE_1M" R0402#1 2970,2810 r270 top
R386 "RES_R0402_DISCRETE_1M" R0402#1 2270,2810 r270 top
R387 "RES_R0402_DISCRETE_22R" R0402#1 2290,2870 r180 top
SS1 "SPACER_NPTH_M3_IC_NPTH_M3" NPTH_M3 137.79,137.79 r0 top
SS2 "SPACER_NPTH_M3_IC_NPTH_M3" NPTH_M3 137.79,3641.73 r0 top
SS3 "SPACER_NPTH_M3_IC_NPTH_M3" NPTH_M3 6673.23,3641.73 r0 top
SS4 "SPACER_NPTH_M3_IC_NPTH_M3" NPTH_M3 6673.23,137.79 r0 top
SS5 "SPACER_SMTSO-M2R5_IC_M2.5X1.5MM" SMTSO-M2R5 1262.06,2343.81 r0 top
SS6 "SPACER_SMTSO-M2R5_IC_M2.5X1.5MM" SMTSO-M2R5 3860.49,2343.81 r0 top
SS7 "SPACER_SMTSO-M2R5_IC_M2.5X1.5MM" SMTSO-M2R5 1262.06,532.79 r0 top
SS8 "SPACER_SMTSO-M2R5_IC_M2.5X1.5MM" SMTSO-M2R5 3860.49,532.79 r0 top
SS9 "SPACER_T3R2-5R2_TOPSMT_IC_M2X3M" T3R2-5R2_TOPSMT 4748.02,509.17 r0 top
SS10 "SPACER_T3R2-5R2_TOPSMT_IC_M2X3M" T3R2-5R2_TOPSMT 5700.78,509.17 r0 top
SS11 "SPACER_SMTSO-M3_IC_M3X3.5MM" SMTSO-M3#1 6340.24,136.22 r0 top
SS12 "SPACER_SMTSO-M3_IC_M3X3.5MM" SMTSO-M3#2 5229.41,1220.89 r0 bottom
SW1 "SW_TH3P_SW_TH_3P_4R5X5R5_IC_TS-" SW_TH_3P_4R5X5R5 1063.11,107.95 r0 top
SW2 "SW_TH3P_SW_TH_3P_4R5X5R5_IC_TS-" SW_TH_3P_4R5X5R5 833.11,107.95 r0 top
SW3 "SW_TH3P_SW_TH_3P_4R5X5R5_IC_TS-" SW_TH_3P_4R5X5R5 603.11,107.95 r0 top
SW4 "SW_TH3P_SW_TH_3P_4R5X5R5_IC_TS-" SW_TH_3P_4R5X5R5 373.11,107.95 r0 top
U1 "TP6327GS6_SOT23_6_ASP9135ZC-R" SOT23_6 690,1979.37 r180 top
U2 "MP8759GD-Z_QFN12-2R00X3R00_MP87" QFN12-2R00X3R00 690,855.04 r0 top
U3 "RTL8211F_QFP_40P_R_RTL8211F" QFP_40P_R 2049.59,2790 r270 top
U4 "RTL8211F_QFP_40P_R_RTL8211F" QFP_40P_R 2774,2790 r270 top
U5 "FUSB302BMPX_WQFN14-0R50-2R5X2R5" WQFN14-0R50-2R5X2R5EP1R45X1R45 785,3125 r0 top
U6 "LPW5209AB5F_SOT23-5_LPW5209AB5F" SOT23-5#1 640,3112.37 r0 bottom
U7 "LPW5209AB5F_SOT23-5_LPW5209AB5F" SOT23-5#2 4770,3669.37 r0 bottom
U8 "RCLAMP0524P_USON_10_RCLAMP0524P" USON_10 1150,3414.37 r0 top
U9 "RCLAMP0524P_USON_10_RCLAMP0524P" USON_10 890,3414.37 r0 top
U10 "RCLAMP0524P_USON_10_RCLAMP0524P" USON_10 4730,3054.37 r0 bottom
U11 "RCLAMP0524P_USON_10_RCLAMP0524P" USON_10 4950,3054.37 r0 bottom
U12 "RCLAMP0524P_USON_10_RCLAMP0524P" USON_10 5555,3084.37 r0 top
U13 "LPW5209AB5F_SOT23-5_LPW5209AB5F" SOT23-5#2 5555,3669.37 r0 bottom
U14 "FE1.1S-BQFN24B_QFN24_FE1.1S-BQF" QFN24 5555,2899.37 r180 top
U15 "IRM-V838M3-C/TR1_SMD4-6R80X2R50" SMD4-6R80X2R50 6390,3692.52 r0 top
U16 "ES8388_QFN28_0R45-4X4EP2R6X2R6_" QFN28_0R45-4X4EP2R6X2R6 805,2705 r0 top
U17 "TP6327GS6_SOT23_6_ASP9135ZC-R" SOT23_6 6220,1845 r270 top
U18 "LPW5209AB5F_SOT23-5_LPW5209AB5F" SOT23-5#3 957.63,2233 r270 top
U19 "SIT3088E-8P_SOP8_IC_SIT3088EESA" SOP8 5390,824.37 r180 top
U23 "RCLAMP0524P_USON_10_RCLAMP0524P" USON_10 4560,2869.37 r0 top
U24 "RCLAMP0524P_USON_10_RCLAMP0524P" USON_10 4400,2869.37 r0 top
U25 "TP6327GS6_SOT23_6_ASP9135ZC-R" SOT23_6 6005,2455 r270 top
U26 "PI6C557-05BLE_TSSOP20_PI6C557-0" TSSOP20 4375,1565 r90 top
U27 "LDO_PT5108_SOT23-5_TP5108E23E-3" SOT23-5#3 5050,1105 r0 top
U28 "TP6327GS6_SOT23_6_ASP9135ZC-R" SOT23_6 690,1514.37 r180 top
U29 "TP6327GS6_SOT23_6_ASP9135ZC-R" SOT23_6 6010,1845 r270 top
U30 "NUP5120-D_SOT563_NUP5120X6T1G" SOT563 6050,795 r0 bottom
U31 "TP6327GS6_SOT23_6_ASP9135ZC-R" SOT23_6 515,2635 r90 top
U32 "TP6327GS6_SOT23_6_ASP9135ZC-R" SOT23_6 690,1754.37 r180 top
U33 "74LVC1G125_SOT-353_74LVC1G125GW" SOT-353 295,500 r90 top
U34 "74LVC1G125_SOT-353_74LVC1G125GW" SOT-353 295,340 r270 top
U35 "HYM8563S_MSOP-8_BM8563EMA" MSOP-8 4730,1105 r0 top
U36 "SIT3088E-8P_SOP8_IC_SIT3088EESA" SOP8 5695,824.37 r180 top
U38 "MAX3232CSE_SOIC16_SIT3232EESE" SOIC16 5291.57,499.37 r90 top
U39 "LPW5209AB5F_SOT23-5_LPW5209AB5F" SOT23-5#4 512.5,3112.37 r0 bottom
U40 "LPW5209AB5F_SOT23-5_LPW5209AB5F" SOT23-5#5 384.5,3112.37 r0 bottom
U41 "LPW5209AB5F_SOT23-5_LPW5209AB5F" SOT23-5#3 617.63,2233 r270 top
U42 "NS4110B_SOP-8-EP-2R5X3R4_NS4110" SOP-8-EP-2R5X3R4 1035,2695 r0 top
U43 "TP6327GS6_SOT23_6_ASP9135ZC-R" SOT23_6 690,1134.37 r180 top
U44 "XL9535_TSSOP24-0R65-7R80X4R40_X" TSSOP24-0R65-7R80X4R40 5225,1650 r270 top
U45 "TJA1057GT3_8P_SOP8_IC_SIT1042AQ" SOP8 4770,824.37 r180 top
U46 "NS4110B_SOP-8-EP-2R5X3R4_NS4110" SOP-8-EP-2R5X3R4 1480,2690 r0 top
U47 "TJA1057GT3_8P_SOP8_IC_SIT1042AQ" SOP8 5090,824.37 r180 top
U48 "LPW5209AB5F_SOT23-5_LPW5209AB5F" SOT23-5#2 4900,3669.37 r0 bottom
Y1 "CRYSTAL_4P_3225_IC_25MHZ" 3225 3090,2850 r270 top
Y2 "CRYSTAL_4P_3225_IC_25MHZ" 3225 2390,2850 r270 top
Y3 "CRYSTAL_4P_3225_IC_12MHZ" 3225 5820,2894.37 r90 top
Y4 "CRYSTAL_4P_3225_IC_25MHZ" 3225 4735,1584.37 r90 top
Y5 "CRYSTAL_2P_3215_32.768KHZ" 3215 4885,1105 r270 top

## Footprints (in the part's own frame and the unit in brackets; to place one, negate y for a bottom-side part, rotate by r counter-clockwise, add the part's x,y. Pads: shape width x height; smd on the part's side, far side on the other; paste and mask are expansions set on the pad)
3215 [mil] "3215"
  rect 55.12x47.24 smd: 1(-39.4,0) 2(39.4,0)
  silkscreen extent -75,-35 75,35, body extent -67,-24 67,24, height 150
3225 [mm] "3225"
  rect 1.3x1 smd: 1(-1.15,-0.75) 2(1.15,-0.75) 3(1.15,0.75) 4(-1.15,0.75)
  silkscreen extent -2.41,-1.52 0.3,1.2, body extent -1.9,-1.4 1.9,1.4, height 3.81
AUDIO_SMD_7P_6R0X8R8 [mm] "AUDIO_SMD_7P_6R0X8R8"
  rect 2.5x1.4 smd: 1(3.45,-3.125) 2(3.45,-0.225) 3(3.45,2.675) 4(-3.45,2.975) 6(-3.45,-2.125) 7(-3.45,0.775) 8(3.45,4.875)
  round 1.2 hole 1.2 unplated: ""(0,3.375) ""(0,-3.625)
  silkscreen extent -3,-7.13 4.25,7.38, body extent -5,-7.63 5,7.63, height 3.81
C0402#1 [mil] "C0402"
  rect 23.6x23.6 smd: 1(-19.68,0) 2(19.68,0)
  silkscreen extent -37,-17 37,17, body extent -37,-17 37,17, height 150
C0402#2 [mil] "C0402"
  rect 23.6x23.6 smd: 1(19.68,0) 2(-19.68,0)
  silkscreen extent -37,-17 37,17, body extent -37,-17 37,17, height 150
C0603#1 [mil] "C0603"
  rect 31.5x31.5 smd: 1(-31.5,0) 2(31.5,0)
  silkscreen extent -55,-25 55,25, body extent -48,-16 48,16, height 150
C0603#2 [mil] "C0603"
  rect 31.5x31.5 smd: 1(31.5,0) 2(-31.5,0)
  silkscreen extent -55,-25 55,25, body extent -48,-16 48,16, height 150
C0805 [mm] "C0805"
  rect 1.16x1.47 smd: 1(-0.89,0) 2(0.89,0)
  silkscreen extent -1.77,-1.04 1.77,1.04, body extent -1.47,-0.74 1.47,0.74, height 3.81
C1206 [mil] "C1206"
  rect 47.24x74.8 smd: 1(-62.99,0) 2(62.99,0)
  silkscreen extent -94,-47 94,47
CASE-B_3528 [mm] "CASE-B_3528"
  rect 1.2x2.4 smd: 1(-1.45,0) 2(1.45,0)
  silkscreen extent -2.9,-1.4 2.2,1.4, body extent -2.1,-1.2 2.1,1.2, height 3.81
DB2ERC-3P81-2P [mm] "DB2ERC-3P81-2P"
  rect 1.8x1.8 / inner round 1.524 / far side rect 1.8x1.8 hole 1.2: 1(-1.905,-3.45)
  round 1.8 / inner round 1.524 / far side round 1.8 hole 1.2: 2(1.905,-3.45)
  silkscreen extent -2.15,-5.3 -1.65,-4.8, body extent -4.4,-4.65 4.4,4.65, height 3.81
DB2ERC-3P81-4P [mm] "DB2ERC-3P81-4P"
  rect 1.8x1.8 / inner round 1.524 / far side rect 1.8x1.8 hole 1.2: 1(-5.725,-3.5)
  round 1.8 / inner round 1.524 / far side round 1.8 hole 1.2: 2(-1.915,-3.5) 3(1.895,-3.5) 4(5.705,-3.5)
  silkscreen extent -8.13,-5.35 8.11,4.55, body extent -8.2,-4.7 8.2,4.7, height 3.81
DB2ERC-3P81-6P [mm] "DB2ERC-3P81-6P"
  rect 1.8x1.8 / inner round 1.524 / far side rect 1.8x1.8 hole 1.2: 1(-9.525,-3.5)
  round 1.8 hole 1.2: 2(-5.715,-3.5) 5(5.715,-3.5)
  round 1.8 / inner round 1.524 / far side round 1.8 hole 1.2: 3(-1.905,-3.5) 4(1.905,-3.5) 6(9.525,-3.5)
  silkscreen extent -11.93,-5.35 11.93,4.55, body extent -12,-4.7 12,4.7, height 3.81
DC_IN_TH_3P_10R1X11R6 [mil] "DC_IN_TH_3P_10R1X11R6"
  oval 94.5x39.4 / inner round 60 / far side oval 94.5x39.4 hole 70.9 slot 15.7 at 90 deg: 1(-111.25,-194.9) 5(-111.25,190.9)
  oval 102.4x43.3 hole 66.9 slot 19.7 at 90 deg: 2(174.25,-51.2) 3(174.25,157.4)
  oval 102.4x43.3 / inner round 60 / far side oval 102.4x43.3 hole 66.9 slot 19.7 at 90 deg: 4(174.25,-177.2)
  round 78.7 hole 78.7 unplated: ""(-69.85,-51.2)
  silkscreen extent -232,-201 226,197, body extent -237,-228 237,228, height 150
DF40C-100DP-0P4V [mm] "DF40C-100DP-0P4V"
  rect 0.2x1.2 smd: 1(-9.8,1.325) 2(-9.8,-1.325) 3(-9.4,1.325) 4(-9.4,-1.325) 5(-9,1.325) 6(-9,-1.325) 7(-8.6,1.325) 8(-8.6,-1.325) 9(-8.2,1.325) 10(-8.2,-1.325) 11(-7.8,1.325) 12(-7.8,-1.325) 13(-7.4,1.325) 14(-7.4,-1.325) 15(-7,1.325) 16(-7,-1.325) 17(-6.6,1.325) 18(-6.6,-1.325) 19(-6.2,1.325) 20(-6.2,-1.325) 21(-5.8,1.325) 22(-5.8,-1.325) 23(-5.4,1.325) 24(-5.4,-1.325) 25(-5,1.325) 26(-5,-1.325) 27(-4.6,1.325) 28(-4.6,-1.325) 29(-4.2,1.325) 30(-4.2,-1.325) 31(-3.8,1.325) 32(-3.8,-1.325) 33(-3.4,1.325) 34(-3.4,-1.325) 35(-3,1.325) 36(-3,-1.325) 37(-2.6,1.325) 38(-2.6,-1.325) 39(-2.2,1.325) 40(-2.2,-1.325) 41(-1.8,1.325) 42(-1.8,-1.325) 43(-1.4,1.325) 44(-1.4,-1.325) 45(-1,1.325) 46(-1,-1.325) 47(-0.6,1.325) 48(-0.6,-1.325) 49(-0.2,1.325) 50(-0.2,-1.325) 51(0.2,1.325) 52(0.2,-1.325) 53(0.6,1.325) 54(0.6,-1.325) 55(1,1.325) 56(1,-1.325) 57(1.4,1.325) 58(1.4,-1.325) 59(1.8,1.325) 60(1.8,-1.325) 61(2.2,1.325) 62(2.2,-1.325) 63(2.6,1.325) 64(2.6,-1.325) 65(3,1.325) 66(3,-1.325) 67(3.4,1.325) 68(3.4,-1.325) 69(3.8,1.325) 70(3.8,-1.325) 71(4.2,1.325) 72(4.2,-1.325) 73(4.6,1.325) 74(4.6,-1.325) 75(5,1.325) 76(5,-1.325) 77(5.4,1.325) 78(5.4,-1.325) 79(5.8,1.325) 80(5.8,-1.325) 81(6.2,1.325) 82(6.2,-1.325) 83(6.6,1.325) 84(6.6,-1.325) 85(7,1.325) 86(7,-1.325) 87(7.4,1.325) 88(7.4,-1.325) 89(7.8,1.325) 90(7.8,-1.325) 91(8.2,1.325) 92(8.2,-1.325) 93(8.6,1.325) 94(8.6,-1.325) 95(9,1.325) 96(9,-1.325) 97(9.4,1.325) 98(9.4,-1.325) 99(9.8,1.325) 100(9.8,-1.325)
  rect 0.35x1.2 smd: 101(-10.275,1.325) 102(-10.275,-1.325) 103(10.275,1.325) 104(10.275,-1.325)
  silkscreen extent -10.8,-0.92 10.8,2.4, body extent -10.9,-2 10.9,2, height 3.81
DF40HC-100DS-0P4V [mm] "DF40HC-100DS-0P4V"
  rect 0.2x0.8 smd: 1(-9.8,-1.7) 2(-9.8,1.7) 3(-9.4,-1.7) 4(-9.4,1.7) 5(-9,-1.7) 6(-9,1.7) 7(-8.6,-1.7) 8(-8.6,1.7) 9(-8.2,-1.7) 10(-8.2,1.7) 11(-7.8,-1.7) 12(-7.8,1.7) 13(-7.4,-1.7) 14(-7.4,1.7) 15(-7,-1.7) 16(-7,1.7) 17(-6.6,-1.7) 18(-6.6,1.7) 19(-6.2,-1.7) 20(-6.2,1.7) 21(-5.8,-1.7) 22(-5.8,1.7) 23(-5.4,-1.7) 24(-5.4,1.7) 25(-5,-1.7) 26(-5,1.7) 27(-4.6,-1.7) 28(-4.6,1.7) 29(-4.2,-1.7) 30(-4.2,1.7) 31(-3.8,-1.7) 32(-3.8,1.7) 33(-3.4,-1.7) 34(-3.4,1.7) 35(-3,-1.7) 36(-3,1.7) 37(-2.6,-1.7) 38(-2.6,1.7) 39(-2.2,-1.7) 40(-2.2,1.7) 41(-1.8,-1.7) 42(-1.8,1.7) 43(-1.4,-1.7) 44(-1.4,1.7) 45(-1,-1.7) 46(-1,1.7) 47(-0.6,-1.7) 48(-0.6,1.7) 49(-0.2,-1.7) 50(-0.2,1.7) 51(0.2,-1.7) 52(0.2,1.7) 53(0.6,-1.7) 54(0.6,1.7) 55(1,-1.7) 56(1,1.7) 57(1.4,-1.7) 58(1.4,1.7) 59(1.8,-1.7) 60(1.8,1.7) 61(2.2,-1.7) 62(2.2,1.7) 63(2.6,-1.7) 64(2.6,1.7) 65(3,-1.7) 66(3,1.7) 67(3.4,-1.7) 68(3.4,1.7) 69(3.8,-1.7) 70(3.8,1.7) 71(4.2,-1.7) 72(4.2,1.7) 73(4.6,-1.7) 74(4.6,1.7) 75(5,-1.7) 76(5,1.7) 77(5.4,-1.7) 78(5.4,1.7) 79(5.8,-1.7) 80(5.8,1.7) 81(6.2,-1.7) 82(6.2,1.7) 83(6.6,-1.7) 84(6.6,1.7) 85(7,-1.7) 86(7,1.7) 87(7.4,-1.7) 88(7.4,1.7) 89(7.8,-1.7) 90(7.8,1.7) 91(8.2,-1.7) 92(8.2,1.7) 93(8.6,-1.7) 94(8.6,1.7) 95(9,-1.7) 96(9,1.7) 97(9.4,-1.7) 98(9.4,1.7) 99(9.8,-1.7) 100(9.8,1.7)
  silkscreen extent -11.3,-2.55 11.3,1.5, body extent -11.4,-2.2 11.4,2.2, height 3.81
ESD0402#1 [mil] "ESD0402"
  rect 23.6x23.6 smd: 1(-19.68,0) 2(19.68,0)
  silkscreen extent -37,-17 37,17, body extent -37,-17 37,17, height 150
ESD0402#2 [mil] "ESD0402"
  rect 23.6x23.6 smd: 1(19.68,0) 2(-19.68,0)
  silkscreen extent -37,-17 37,17, body extent -37,-17 37,17, height 150
F1812 [mm] "F1812"
  rect 1.78x3.3 smd: 1(-2.305,0) 2(2.305,0)
  silkscreen extent -3.4,-1.9 3.4,1.9, body extent -3.4,-1.9 3.4,1.9, height 3.81
FPC-30P-0P5 [mm] "FPC-30P-0P5"
  rect 0.3x1.3 smd: 1(-7.25,2.733) 2(-6.75,2.733) 3(-6.25,2.733) 4(-5.75,2.733) 5(-5.25,2.733) 6(-4.75,2.733) 7(-4.25,2.733) 8(-3.75,2.733) 9(-3.25,2.733) 10(-2.75,2.733) 11(-2.25,2.733) 12(-1.75,2.733) 13(-1.25,2.733) 14(-0.75,2.733) 15(-0.25,2.733) 16(0.25,2.733) 17(0.75,2.733) 18(1.25,2.733) 19(1.75,2.733) 20(2.25,2.733) 21(2.75,2.733) 22(3.25,2.733) 23(3.75,2.733) 24(4.25,2.733) 25(4.75,2.733) 26(5.25,2.733) 27(5.75,2.733) 28(6.25,2.733) 29(6.75,2.733) 30(7.25,2.733)
  rect 1.6x2 smd: 31(9.4,0.032) 32(-9.4,0.032)
  silkscreen extent -10.05,-3.27 10.05,4.14, body extent -10.05,-3.35 10.05,3.35, height 3.81
FPC_24P_0P5 [mm] "FPC_24P_0P5"
  rect 0.3x1.3 smd: 1(-5.75,-2.701) 2(-5.25,-2.701) 3(-4.75,-2.701) 4(-4.25,-2.701) 5(-3.75,-2.701) 6(-3.25,-2.701) 7(-2.75,-2.701) 8(-2.25,-2.701) 9(-1.75,-2.701) 10(-1.25,-2.701) 11(-0.75,-2.701) 12(-0.25,-2.701) 13(0.25,-2.701) 14(0.75,-2.701) 15(1.25,-2.701) 16(1.75,-2.701) 17(2.25,-2.701) 18(2.75,-2.701) 19(3.25,-2.701) 20(3.75,-2.701) 21(4.25,-2.701) 22(4.75,-2.701) 23(5.25,-2.701) 24(5.75,-2.701)
  rect 1.6x2 smd: 25(7.45,0.001) 26(-7.45,0.001)
  silkscreen extent -8.1,-3.95 8.1,3.35, body extent -8.1,-3.35 8.1,3.35, height 3.81
GH1P25_TH_2P [mm] "GH1P25_TH_2P"
  rect 0.9x0.9 / inner round 1.524 / far side rect 0.9x0.9 hole 0.5: 1(-0.626,-0.849)
  round 0.9 hole 0.5: 2(0.624,-0.849)
  silkscreen extent -2.2,-1.75 2.2,1.75, body extent -2.33,-1.88 2.33,1.88, height 3.81
HDMI-SMD [mm] "HDMI-SMD"
  round 0.8 / inner round 1.524 / far side round 0.8 hole 0.55: 1(1.276,0.5) 3(0.121,0.5) 4(-0.449,-0.5) 6(-1.605,-0.5) 7(-2.189,0.5) 9(-3.344,0.5) 10(-3.917,-0.5) 12(-5.073,-0.5) 13(-5.654,0.5) 14(-6.229,-0.5) 15(-6.809,0.5) 16(-7.385,-0.5) 18(-8.541,-0.5) 19(-9.119,0.5)
  round 0.8 hole 0.55: 2(0.707,-0.5) 5(-1.034,0.5) 8(-2.761,-0.5) 11(-4.499,0.5) 17(-7.964,0.5)
  oval 3.2x1.4 / inner round 1.524 / far side oval 3.2x1.4 hole 2.7 slot 0.9 at 90 deg: G1(-10.074,3.25) G2(-0.574,3.25) G3(-6.974,-3.25) G4(2.026,-3.25)
  round 1.999 hole 1.999 unplated: ""(-10.074,-2) ""(3.176,1.5)
  silkscreen extent -11.43,-5.02 19.77,5, body extent -11.78,-4.05 11.78,4.05, height 3.81
HDR1X3-2R54-TM-VM [mm] "HDR1X3-2R54-TM-VM"
  rect 1.6x1.6 / inner round 1.524 / far side rect 1.6x1.6 hole 1: 1(-2.535,0)
  round 1.6 / inner round 1.524 / far side round 1.6 hole 1: 2(0.005,0)
  round 1.6 hole 1: 3(2.545,0)
  silkscreen extent -3.8,-1.25 3.82,1.25, body extent -3.8,-1.25 3.8,1.25, height 3.81
HDR2X3-2R54-TM-VM [mm] "HDR2X3-2R54-TM-VM"
  rect 1.6x1.6 / inner round 1.524 / far side rect 1.6x1.6 hole 1: 1(-2.54,-1.27)
  round 1.6 / inner round 1.524 / far side round 1.6 hole 1: 2(-2.54,1.27) 3(0,-1.27) 4(0,1.27) 5(2.54,-1.27) 6(2.54,1.27)
  silkscreen extent -3.77,-2.5 3.77,2.5, body extent -3.8,-2.5 3.8,2.5, height 3.81
HY911130A#1 [mm] "HY911130A"
  round 1.6 / inner round 1.524 / far side round 1.6 hole 1: 1(5.629,-8.79) 2(4.359,-6.25) 3(3.089,-8.79) 4(1.819,-6.25) 5(0.549,-8.79) 6(-0.721,-6.25) 7(-1.991,-8.79) 8(-3.261,-6.25) 9(-4.531,-8.79)
  round 1.6 hole 1: 10(-5.801,-6.25)
  round 1.8 / inner round 1.524 / far side round 1.8 hole 1.2: 11(6.534,5) 12(3.994,5) 13(-4.177,5) 14(-6.717,5)
  round 2.43 / inner round 1.524 / far side round 2.43 hole 1.83: 15(7.654,-2.95) 16(-7.836,-2.95)
  round 3.25 hole 3.25 unplated: ""(-5.806,0.1) ""(5.624,0.1)
  silkscreen extent -8.11,-10.3 7.93,17.1, body extent -9.11,-11.1 9.11,11.1, height 3.81
HY911130A#2 [mm] "HY911130A"
  round 1.6 / inner round 1.524 / far side round 1.6 hole 1: 1(5.319,-8.79) 2(4.049,-6.25) 3(2.779,-8.79) 4(1.509,-6.25) 5(0.239,-8.79) 6(-1.031,-6.25) 7(-2.301,-8.79) 8(-3.571,-6.25) 9(-4.841,-8.79)
  round 1.6 hole 1: 10(-6.111,-6.25)
  round 1.8 / inner round 1.524 / far side round 1.8 hole 1.2: 11(6.224,5) 12(3.684,5) 13(-4.487,5) 14(-7.027,5)
  round 2.43 / inner round 1.524 / far side round 2.43 hole 1.83: 15(7.343,-2.95) 16(-8.146,-2.95)
  round 3.25 hole 3.25 unplated: ""(-6.116,0.1) ""(5.314,0.1)
  silkscreen extent -8.42,-10.3 7.62,17.1, body extent -8.8,-11.1 8.8,11.1, height 3.81
L0518 [mm] "L0518"
  rect 1.9x2.5 smd: 1(-2.05,0) 2(2.05,0)
  silkscreen extent -2.75,-2.65 2.75,2.65, body extent -3.1,-2.8 3.1,2.8, height 3.81
L0603#1 [mil] "L0603"
  rect 31.5x31.5 smd: 1(-31.5,0) 2(31.5,0)
  silkscreen extent -55,-24 55,24, body extent -47,-16 47,16, height 150
L0603#2 [mil] "L0603"
  rect 31.5x31.5 smd: 1(31.5,0) 2(-31.5,0)
  silkscreen extent -55,-24 54,24, body extent -47,-16 47,16, height 150
L2520 [mil] "L2520"
  rect 44x80 smd: 1(-37.75,0) 2(37.75,0)
  silkscreen extent -68,-48 68,48, body extent -65,-45 65,45, height 150
L4520 [mil] "L4520"
  rect 55.12x90.55 smd: 1(-70.97,-0.1) 2(70.77,-0.1)
  silkscreen extent -91,-87 90,87, body extent -91,-87 91,87, height 150
LED_HS_0602_UR [mil] "LED_HS_0602_UR"
  rect 30.3x23.6 smd: 1(-32.1,-15.75) 2(32.1,-15.75)
  silkscreen extent -54,-28 32,28
M2_NGFF_E_KEY [mm] "M2_NGFF_E_KEY"
  rect 0.3x1.55 smd: 1(9.25,-3.3) 2(9,4.25) 3(8.75,-3.3) 4(8.5,4.25) 5(8.25,-3.3) 6(8,4.25) 7(7.75,-3.3) 8(7.5,4.25) 9(7.25,-3.3) 10(7,4.25) 11(6.75,-3.3) 12(6.5,4.25) 13(6.25,-3.3) 14(6,4.25) 15(5.75,-3.3) 16(5.5,4.25) 17(5.25,-3.3) 18(5,4.25) 19(4.75,-3.3) 20(4.5,4.25) 21(4.25,-3.3) 22(4,4.25) 23(3.75,-3.3) 32(1.5,4.25) 33(1.25,-3.3) 34(1,4.25) 35(0.75,-3.3) 36(0.5,4.25) 37(0.25,-3.3) 38(0,4.25) 39(-0.25,-3.3) 40(-0.5,4.25) 41(-0.75,-3.3) 42(-1,4.25) 43(-1.25,-3.3) 44(-1.5,4.25) 45(-1.75,-3.3) 46(-2,4.25) 47(-2.25,-3.3) 48(-2.5,4.25) 49(-2.75,-3.3) 50(-3,4.25) 51(-3.25,-3.3) 52(-3.5,4.25) 53(-3.75,-3.3) 54(-4,4.25) 55(-4.25,-3.3) 56(-4.5,4.25) 57(-4.75,-3.3) 58(-5,4.25) 59(-5.25,-3.3) 60(-5.5,4.25) 61(-5.75,-3.3) 62(-6,4.25) 63(-6.25,-3.3) 64(-6.5,4.25) 65(-6.75,-3.3) 66(-7,4.25) 67(-7.25,-3.3) 68(-7.5,4.25) 69(-7.75,-3.3) 70(-8,4.25) 71(-8.25,-3.3) 72(-8.5,4.25) 73(-8.75,-3.3) 74(-9,4.25) 75(-9.25,-3.3)
  rect 1.2x2.75 smd: 76(10.35,-2.525) 77(-10.35,-2.525)
  round 1.6 hole 1.6 unplated: ""(-10,1.975)
  round 1.1 hole 1.1 unplated: ""(10,1.975)
  silkscreen extent -11,-1.13 11,4.12, body extent -11,-4.13 11,4.12, height 3.81
M2_NGFF_M_KEY [mm] "M2_NGFF_M_KEY"
  rect 0.3x1.55 smd: 1(-9.25,3.762) 2(-9,-3.687) 3(-8.75,3.762) 4(-8.5,-3.687) 5(-8.25,3.762) 6(-8,-3.687) 7(-7.75,3.762) 8(-7.5,-3.687) 9(-7.25,3.762) 10(-7,-3.687) 11(-6.75,3.762) 12(-6.5,-3.687) 13(-6.25,3.762) 14(-6,-3.687) 15(-5.75,3.762) 16(-5.5,-3.687) 17(-5.25,3.762) 18(-5,-3.687) 19(-4.75,3.762) 20(-4.5,-3.687) 21(-4.25,3.762) 22(-4,-3.687) 23(-3.75,3.762) 24(-3.5,-3.687) 25(-3.25,3.762) 26(-3,-3.687) 27(-2.75,3.762) 28(-2.5,-3.687) 29(-2.25,3.762) 30(-2,-3.687) 31(-1.75,3.762) 32(-1.5,-3.687) 33(-1.25,3.762) 34(-1,-3.687) 35(-0.75,3.762) 36(-0.5,-3.687) 37(-0.25,3.762) 38(0,-3.687) 39(0.25,3.762) 40(0.5,-3.687) 41(0.75,3.762) 42(1,-3.687) 43(1.25,3.762) 44(1.5,-3.687) 45(1.75,3.762) 46(2,-3.687) 47(2.25,3.762) 48(2.5,-3.687) 49(2.75,3.762) 50(3,-3.687) 51(3.25,3.762) 52(3.5,-3.687) 53(3.75,3.762) 54(4,-3.687) 55(4.25,3.762) 56(4.5,-3.687) 57(4.75,3.762) 58(5,-3.687) 67(7.25,3.762) 68(7.5,-3.687) 69(7.75,3.762) 70(8,-3.687) 71(8.25,3.762) 72(8.5,-3.687) 73(8.75,3.762) 74(9,-3.687) 75(9.25,3.762)
  rect 1.2x2.75 smd: 76(10.35,3.062) 77(-10.35,3.062)
  round 1.1 hole 1.1 unplated: ""(-10,-1.438)
  round 1.6 hole 1.6 unplated: ""(10,-1.438)
  silkscreen extent -10.95,-81.8 10.95,1.61, body extent -10.95,-4.56 10.95,4.56, height 3.81
MARK#1 [mil] "MARK"
  round 40 smd: 1(-724.11,3646.43) 1(-300,3976.38) 1(0,0) 1(90.89,946.42) 1(4874.8,0) 1(4874.8,3976.38) 1(4875.89,225.43) 1(5148.89,2479.43)
  round 40 smd far side: 1(-499.11,632.42) 1(-17.11,3457.43) 1(4728.89,441.43) 1(5023.89,3605.43)
  body extent -539,-40 5064,4016, height 150
MARK#2 [mil] "MARK"
  round 40 smd: 1(-5598.91,3646.43) 1(-5174.8,3976.38) 1(-4874.8,0) 1(-4783.91,946.42) 1(0,0) 1(0,3976.38) 1(1.09,225.43) 1(274.09,2479.43)
  round 40 smd far side: 1(-5373.91,632.42) 1(-4891.91,3457.43) 1(-145.91,441.43) 1(149.09,3605.43)
  body extent -5414,-40 189,4016, height 150
MARK#3 [mil] "MARK"
  round 40 smd: 1(-274.09,1496.95) 1(-1.09,3750.95) 1(0,3976.38) 1(0,0) 1(4783.91,3029.95) 1(4874.8,3976.38) 1(5174.8,0) 1(5598.91,329.95)
  round 40 smd far side: 1(-149.09,370.95) 1(145.91,3534.95) 1(4891.91,518.95) 1(5373.91,3343.95)
  body extent -189,-40 5414,4016, height 150
MARK#4 [mil] "MARK"
  round 40 smd: 1(-5448.89,1496.95) 1(-5175.89,3750.95) 1(-5174.8,3976.38) 1(-5174.8,0) 1(-390.89,3029.95) 1(-300,3976.38) 1(0,0) 1(424.11,329.95)
  round 40 smd far side: 1(-5323.89,370.95) 1(-5028.89,3534.95) 1(-282.89,518.95) 1(199.11,3343.95)
  body extent -5364,-40 239,4016, height 150
MARK#5 [mil] "MARK"
  round 40 smd far side: 1(-724.11,-3646.43) 1(-300,-3976.38) 1(0,0) 1(90.89,-946.42) 1(4874.8,-3976.38) 1(4874.8,0) 1(4875.89,-225.43) 1(5148.89,-2479.43)
  round 40 smd: 1(-499.11,-632.42) 1(-17.11,-3457.43) 1(4728.89,-441.43) 1(5023.89,-3605.43)
  body extent -539,-4016 5064,40, height 150
MARK#6 [mil] "MARK"
  round 40 smd far side: 1(-424.11,329.95) 1(0,0) 1(300,3976.38) 1(390.89,3029.95) 1(5174.8,0) 1(5174.8,3976.38) 1(5175.89,3750.95) 1(5448.89,1496.95)
  round 40 smd: 1(-199.11,3343.95) 1(282.89,518.95) 1(5028.89,3534.95) 1(5323.89,370.95)
  body extent -239,-40 5364,4016, height 150
MARK#7 [mil] "MARK"
  round 40 smd far side: 1(-5598.91,329.95) 1(-5174.8,0) 1(-4874.8,3976.38) 1(-4783.91,3029.95) 1(0,0) 1(0,3976.38) 1(1.09,3750.95) 1(274.09,1496.95)
  round 40 smd: 1(-5373.91,3343.95) 1(-4891.91,518.95) 1(-145.91,3534.95) 1(149.09,370.95)
  body extent -5414,-40 189,4016, height 150
MARK#8 [mil] "MARK"
  round 40 smd far side: 1(-5598.91,-3646.43) 1(-5174.8,-3976.38) 1(-4874.8,0) 1(-4783.91,-946.42) 1(0,-3976.38) 1(0,0) 1(1.09,-225.43) 1(274.09,-2479.43)
  round 40 smd: 1(-5373.91,-632.42) 1(-4891.91,-3457.43) 1(-145.91,-441.43) 1(149.09,-3605.43)
  body extent -5414,-4016 189,40, height 150
MARK#9 [mil] "MARK"
  round 40 smd: 1(-815,2700) 1(-390.89,3029.95) 1(-90.89,-946.42) 1(0,0) 1(4783.91,-946.42) 1(4783.91,3029.95) 1(4785,-721) 1(5058,1533)
  round 40 smd far side: 1(-590,-314) 1(-108,2511) 1(4638,-505) 1(4933,2659)
  body extent -630,-986 4973,3070, height 150
MARK#10 [mil] "MARK"
  round 40 smd: 1(0,0) 1(424.11,329.95) 1(724.11,-3646.43) 1(815,-2700) 1(5598.91,-3646.43) 1(5598.91,329.95) 1(5600,-3421) 1(5873,-1167)
  round 40 smd far side: 1(225,-3014) 1(707,-189) 1(5453,-3205) 1(5748,-41)
  body extent 185,-3686 5788,370, height 150
MARK#11 [mil] "MARK"
  round 40 smd: 1(-5600,3421) 1(-5175.89,3750.95) 1(-4875.89,-225.43) 1(-4785,721) 1(-1.09,-225.43) 1(-1.09,3750.95) 1(0,0) 1(273,2254)
  round 40 smd far side: 1(-5375,407) 1(-4893,3232) 1(-147,216) 1(148,3380)
  body extent -5415,-265 188,3791, height 150
MARK#12 [mil] "MARK"
  round 40 smd: 1(-5873,1167) 1(-5448.89,1496.95) 1(-5148.89,-2479.43) 1(-5058,-1533) 1(-274.09,-2479.43) 1(-274.09,1496.95) 1(-273,-2254) 1(0,0)
  round 40 smd far side: 1(-5648,-1847) 1(-5166,978) 1(-420,-2038) 1(-125,1126)
  body extent -5688,-2519 -85,1537, height 150
MARK#13 [mil] "MARK"
  round 40 smd far side: 1(-225,-3014) 1(199.11,-3343.95) 1(499.11,632.42) 1(590,-314) 1(5373.91,-3343.95) 1(5373.91,632.42) 1(5375,407) 1(5648,-1847)
  round 40 smd: 1(0,0) 1(482,-2825) 1(5228,191) 1(5523,-2973)
  body extent -40,-3384 5563,672, height 150
MARK#14 [mil] "MARK"
  round 40 smd far side: 1(-707,-189) 1(-282.89,-518.95) 1(17.11,3457.43) 1(108,2511) 1(4891.91,-518.95) 1(4891.91,3457.43) 1(4893,3232) 1(5166,978)
  round 40 smd: 1(-482,2825) 1(0,0) 1(4746,3016) 1(5041,-148)
  body extent -522,-559 5081,3497, height 150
